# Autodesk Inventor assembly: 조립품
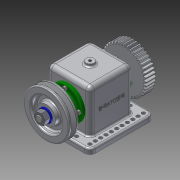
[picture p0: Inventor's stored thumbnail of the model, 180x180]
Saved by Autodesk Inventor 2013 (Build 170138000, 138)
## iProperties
Created: 2018-11
Part Number: 조립품
Document SubType Name: Assembly
Designer: Administrator
Author: Administrator
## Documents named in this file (13)
- C:\Users\Administrator\Desktop\481107V1025\조립품.iam
- C:\Users\Administrator\Desktop\481107V1025\본체.ipt
- C:\Users\Administrator\Desktop\481107V1025\V벨트풀리.ipt
- C:\Users\Administrator\Desktop\481107V1025\너트 M12x1.25.ipt
- C:\Users\Administrator\Desktop\481107V1025\베어링 6203.ipt
- C:\Users\Administrator\Desktop\481107V1025\볼트 M4.ipt
- C:\Users\Administrator\Desktop\481107V1025\부시.ipt
- C:\Users\Administrator\Desktop\481107V1025\스퍼기어.ipt
- C:\Users\Administrator\Desktop\481107V1025\오일 실 26 38 8.ipt
- C:\Users\Administrator\Desktop\481107V1025\와셔 12x24.ipt
- C:\Users\Administrator\Desktop\481107V1025\축.ipt
- C:\Users\Administrator\Desktop\481107V1025\커버.ipt
- C:\Users\Administrator\Desktop\481107V1025\키 5x5x12.ipt
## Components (1 placed, 1 different names)
1. V벨트풀리:1
